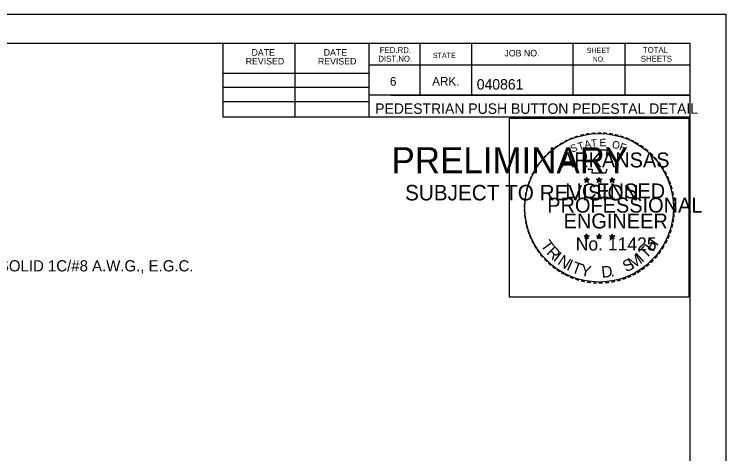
# Model space of a CAD drawing. Extents: x 1370050 to 1370716, y 380076 to 380502.
# Drawn here: x 1370525.6 to 1370716.4, y 380384.6 to 380502.4 of the extents above; entities that cross this region are included whole.
import ezdxf

# ---------------------------------------------------------------- set-up
doc = ezdxf.new("R2010")
doc.units = 0
for name, color, linetype in [('R_Border', 7, 'Continuous'), ('R_Border PE', 7, 'Continuous'), ('R_Border Prem', 7, 'Continuous'), ('R_Grid', 7, 'Continuous'), ('R_No Plot', 7, 'Continuous')]:
    doc.layers.add(name, color=color, linetype=linetype)

msp = doc.modelspace()

# ---------------------------------------------------------------- linework, layer by layer
at = {"layer": 'R_Border'}
for p, q in [((1370074.49, 380494.58), (1370706.85, 380494.58)), ((1370581.57, 380474.82), (1370581.57, 380494.58)), ((1370600.93, 380474.82), (1370600.93, 380494.58)), ((1370620.65, 380494.58), (1370620.65, 380474.82)), ((1370634.33, 380494.58), (1370634.33, 380480.7)), ((1370648.21, 380494.58), (1370648.21, 380480.7)), ((1370675.37, 380494.58), (1370675.37, 380480.7)), ((1370689.25, 380494.58), (1370689.25, 380480.7)), ((1370706.85, 380083.66), (1370706.85, 380494.58)), ((1370706.85, 380488.74), (1370706.85, 380488.74)), ((1370706.85, 380488.7), (1370620.65, 380488.7)), ((1370581.57, 380486.54), (1370620.65, 380486.54)), ((1370581.57, 380482.82), (1370620.65, 380482.82)), ((1370706.85, 380480.7), (1370620.65, 380480.7)), ((1370626.57, 380480.7), (1370706.85, 380480.7)), ((1370581.57, 380478.94), (1370620.65, 380478.94)), ((1370706.85, 380474.82), (1370581.57, 380474.82))]:
    msp.add_line(p, q, dxfattribs=at)
at = {"layer": 'R_Border PE'}
for p, q in [((1370679.06, 380458.65), (1370678.98, 380458.14)), ((1370679.06, 380457.92), (1370679.06, 380458.65)), ((1370679.06, 380458.65), (1370679.16, 380458.15)), ((1370682.4, 380458.65), (1370682.32, 380458.14)), ((1370682.4, 380457.92), (1370682.4, 380458.65)), ((1370682.4, 380458.65), (1370682.5, 380458.15)), ((1370685.93, 380458.62), (1370685.84, 380458.12)), ((1370685.93, 380457.89), (1370685.93, 380458.62)), ((1370685.93, 380458.62), (1370686.02, 380458.12)), ((1370678.36, 380458.14), (1370679.06, 380457.92)), ((1370678.36, 380458.14), (1370678.87, 380458.05)), ((1370678.36, 380458.14), (1370678.83, 380457.9)), ((1370678.63, 380457.32), (1370679.06, 380457.92)), ((1370678.63, 380457.32), (1370678.88, 380457.81)), ((1370678.63, 380457.32), (1370679.05, 380457.76)), ((1370679.48, 380457.32), (1370679.05, 380457.75)), ((1370679.75, 380458.14), (1370679.06, 380457.92)), ((1370679.48, 380457.32), (1370679.06, 380457.92)), ((1370679.75, 380458.14), (1370679.18, 380458.04)), ((1370679.48, 380457.32), (1370679.21, 380457.91)), ((1370679.75, 380458.14), (1370679.34, 380457.94)), ((1370681.7, 380458.14), (1370682.4, 380457.92)), ((1370681.7, 380458.14), (1370682.21, 380458.05)), ((1370681.7, 380458.14), (1370682.17, 380457.9)), ((1370681.97, 380457.32), (1370682.4, 380457.92)), ((1370681.97, 380457.32), (1370682.22, 380457.81)), ((1370681.97, 380457.32), (1370682.39, 380457.76)), ((1370682.82, 380457.32), (1370682.39, 380457.75)), ((1370683.09, 380458.14), (1370682.4, 380457.92)), ((1370682.82, 380457.32), (1370682.4, 380457.92)), ((1370683.09, 380458.14), (1370682.52, 380458.04)), ((1370682.82, 380457.32), (1370682.55, 380457.91)), ((1370683.09, 380458.14), (1370682.68, 380457.94)), ((1370685.23, 380458.12), (1370685.93, 380457.89)), ((1370685.23, 380458.12), (1370685.73, 380458.03)), ((1370685.23, 380458.12), (1370685.7, 380457.87)), ((1370685.49, 380457.3), (1370685.93, 380457.89)), ((1370685.49, 380457.3), (1370685.75, 380457.79)), ((1370685.49, 380457.3), (1370685.92, 380457.73)), ((1370686.35, 380457.3), (1370685.92, 380457.73)), ((1370686.62, 380458.12), (1370685.93, 380457.89)), ((1370686.35, 380457.3), (1370685.93, 380457.89)), ((1370686.62, 380458.12), (1370686.05, 380458.02)), ((1370686.35, 380457.3), (1370686.08, 380457.88)), ((1370686.62, 380458.12), (1370686.21, 380457.91)), ((1370678.35, 380442.99), (1370679.05, 380442.77)), ((1370678.35, 380442.99), (1370678.86, 380442.9)), ((1370678.35, 380442.99), (1370678.83, 380442.75)), ((1370679.05, 380443.5), (1370678.97, 380443)), ((1370679.05, 380442.77), (1370679.05, 380443.5)), ((1370679.05, 380443.5), (1370679.15, 380443)), ((1370679.74, 380442.99), (1370679.05, 380442.77)), ((1370679.74, 380442.99), (1370679.17, 380442.9)), ((1370679.74, 380442.99), (1370679.34, 380442.79)), ((1370681.69, 380442.99), (1370682.39, 380442.77)), ((1370681.69, 380442.99), (1370682.2, 380442.9)), ((1370681.69, 380442.99), (1370682.16, 380442.75)), ((1370682.39, 380443.5), (1370682.31, 380443)), ((1370682.39, 380442.77), (1370682.39, 380443.5)), ((1370682.39, 380443.5), (1370682.49, 380443)), ((1370683.08, 380442.99), (1370682.39, 380442.77)), ((1370683.08, 380442.99), (1370682.51, 380442.9)), ((1370683.08, 380442.99), (1370682.67, 380442.79)), ((1370685.22, 380442.97), (1370685.92, 380442.75)), ((1370685.22, 380442.97), (1370685.73, 380442.88)), ((1370685.22, 380442.97), (1370685.7, 380442.73)), ((1370685.92, 380443.48), (1370685.84, 380442.98)), ((1370685.92, 380442.75), (1370685.92, 380443.48)), ((1370685.92, 380443.48), (1370686.02, 380442.98)), ((1370686.62, 380442.97), (1370685.92, 380442.75)), ((1370686.62, 380442.97), (1370686.04, 380442.88)), ((1370686.62, 380442.97), (1370686.21, 380442.77)), ((1370678.62, 380442.18), (1370679.05, 380442.77)), ((1370678.62, 380442.18), (1370678.87, 380442.67)), ((1370678.62, 380442.18), (1370679.05, 380442.61)), ((1370679.48, 380442.18), (1370679.05, 380442.77)), ((1370679.48, 380442.18), (1370679.05, 380442.61)), ((1370679.48, 380442.18), (1370679.2, 380442.76)), ((1370681.96, 380442.18), (1370682.39, 380442.77)), ((1370681.96, 380442.18), (1370682.21, 380442.67)), ((1370681.96, 380442.18), (1370682.38, 380442.61)), ((1370682.81, 380442.18), (1370682.38, 380442.61)), ((1370682.81, 380442.18), (1370682.39, 380442.77)), ((1370682.81, 380442.18), (1370682.54, 380442.76)), ((1370685.49, 380442.16), (1370685.92, 380442.75)), ((1370685.49, 380442.16), (1370685.74, 380442.65)), ((1370685.49, 380442.16), (1370685.92, 380442.59)), ((1370686.35, 380442.16), (1370685.92, 380442.75)), ((1370686.35, 380442.16), (1370685.92, 380442.59)), ((1370686.35, 380442.16), (1370686.07, 380442.74))]:
    msp.add_line(p, q, dxfattribs=at)
for points in [[(1370678.44, 380465.9), (1370678.98, 380464.24)], [(1370685.46, 380464.05), (1370685.75, 380464.62), (1370684.38, 380464.57), (1370684.67, 380465.9), (1370678.44, 380465.9)], [(1370679.43, 380461.05), (1370679.43, 380460.88), (1370680.55, 380460.84), (1370680.44, 380459.89), (1370684.18, 380459.89), (1370684.59, 380460.96)], [(1370679.06, 380458.65), (1370679.48, 380457.32), (1370678.36, 380458.14), (1370679.75, 380458.14), (1370678.63, 380457.32), (1370679.06, 380458.65)], [(1370682.4, 380458.65), (1370682.82, 380457.32), (1370681.7, 380458.14), (1370683.09, 380458.14), (1370681.97, 380457.32), (1370682.4, 380458.65)], [(1370685.93, 380458.62), (1370686.35, 380457.3), (1370685.23, 380458.12), (1370686.62, 380458.12), (1370685.49, 380457.3), (1370685.93, 380458.62)], [(1370679.05, 380443.5), (1370679.48, 380442.18), (1370678.35, 380442.99), (1370679.74, 380442.99), (1370678.62, 380442.18), (1370679.05, 380443.5)], [(1370682.39, 380443.5), (1370682.81, 380442.18), (1370681.69, 380442.99), (1370683.08, 380442.99), (1370681.96, 380442.18), (1370682.39, 380443.5)], [(1370685.92, 380443.48), (1370686.35, 380442.16), (1370685.22, 380442.97), (1370686.62, 380442.97), (1370685.49, 380442.16), (1370685.92, 380443.48)]]:
    msp.add_lwpolyline(points, dxfattribs=at)
for centre, radius in [((1370679.06, 380457.92), 0.344), ((1370682.4, 380457.92), 0.344), ((1370685.92, 380457.89), 0.344), ((1370679.06, 380457.92), 0.289), ((1370679.06, 380457.92), 0.231), ((1370679.06, 380457.92), 0.198), ((1370679.06, 380457.92), 0.149), ((1370679.06, 380457.92), 0.0991), ((1370679.06, 380457.92), 0.0593), ((1370682.4, 380457.92), 0.289), ((1370682.4, 380457.92), 0.231), ((1370682.4, 380457.92), 0.198), ((1370682.4, 380457.92), 0.149), ((1370682.4, 380457.92), 0.0991), ((1370682.4, 380457.92), 0.0593), ((1370685.92, 380457.89), 0.289), ((1370685.92, 380457.89), 0.231), ((1370685.92, 380457.89), 0.198), ((1370685.92, 380457.89), 0.149), ((1370685.92, 380457.89), 0.0991), ((1370685.92, 380457.89), 0.0593), ((1370679.05, 380442.77), 0.344), ((1370679.05, 380442.77), 0.289), ((1370679.05, 380442.77), 0.231), ((1370679.05, 380442.77), 0.198), ((1370682.39, 380442.77), 0.344), ((1370682.39, 380442.77), 0.289), ((1370682.39, 380442.77), 0.231), ((1370682.39, 380442.77), 0.198), ((1370685.92, 380442.75), 0.344), ((1370685.92, 380442.75), 0.289), ((1370685.92, 380442.75), 0.231), ((1370685.92, 380442.75), 0.198), ((1370679.05, 380442.77), 0.149), ((1370679.05, 380442.77), 0.0991), ((1370679.05, 380442.77), 0.0593), ((1370682.39, 380442.77), 0.149), ((1370682.39, 380442.77), 0.0991), ((1370682.39, 380442.77), 0.0593), ((1370685.92, 380442.75), 0.149), ((1370685.92, 380442.75), 0.0991), ((1370685.92, 380442.75), 0.0593)]:
    msp.add_circle(centre, radius, dxfattribs=at)
at = {"layer": 'R_No Plot'}
for p, q in [((1370049.68, 380502.37), (1370716.35, 380502.37)), ((1370658.26, 380428.72), (1370658.26, 380428.72))]:
    msp.add_line(p, q, dxfattribs=at)
for points in [[(1370049.67, 380502.37), (1370716.35, 380502.37), (1370716.35, 380075.69), (1370049.67, 380075.69)], [(1370658.41, 380474.51), (1370706.41, 380474.51), (1370706.41, 380426.51), (1370658.41, 380426.51)]]:
    msp.add_lwpolyline(points, close=True, dxfattribs=at)
msp.add_circle((1370682.41, 380450.51), 19.9, dxfattribs=at)

# ---------------------------------------------------------------- texts
at = {"layer": 'R_Border'}
for s, height, p in [('DATE', 1.758, (1370589.21, 380491.26)), ('DATE', 1.758, (1370608.57, 380491.26)), ('FED.RD.', 1.564, (1370623.61, 380492.02)), ('JOB NO.', 1.758, (1370657.01, 380491.06)), ('SHEET', 1.368, (1370679.09, 380492.02)), ('TOTAL', 1.564, (1370694.13, 380492.02)), ('REVISED', 1.758, (1370587.65, 380488.9)), ('REVISED', 1.758, (1370607.01, 380488.9)), ('DIST.NO.', 1.564, (1370623.21, 380489.66)), ('STATE', 1.368, (1370637.85, 380490.66)), ('NO.', 1.368, (1370680.65, 380489.66)), ('SHEETS', 1.564, (1370693.57, 380489.66)), ('6', 2.34, (1370626.33, 380483.22)), ('ARK.', 2.345, (1370637.65, 380483.22)), ('040861', 2.8, (1370649.6, 380482.18)), ('PEDESTRIAN PUSH BUTTON PEDESTAL DETAIL', 2.8, (1370622.37, 380475.68))]:
    msp.add_text(s, height=height, dxfattribs=at).set_placement(p)
at = {"layer": 'R_Border PE'}
for s, height, rotation, p in [('-', 3.2, 19.1761, (1370675.94, 380468.15)), ('-', 3.2, 13.6302, (1370677.44, 380468.63)), ('-', 3.2, 10.2193, (1370678.79, 380468.96)), ('-', 3.2, 5.8968, (1370680.25, 380469.18)), ('-', 3.2, 0.1862, (1370681.79, 380469.32)), ('-', 3.2, 357.743, (1370683.24, 380469.29)), ('-', 3.2, 352.1617, (1370684.73, 380469.18)), ('-', 3.2, 347.2049, (1370686.17, 380468.95)), ('-', 3.2, 342.3362, (1370687.44, 380468.64)), ('-', 3.2, 34.0636, (1370672.21, 380466.24)), ('-', 3.2, 28.7918, (1370673.4, 380466.98)), ('-', 3.2, 24.3072, (1370674.67, 380467.61)), ('T', 2, 16.4036, (1370676.98, 380465.91)), ('A', 2, 11.2132, (1370678.63, 380466.42)), ('T', 2, 6.0228, (1370680.33, 380466.75)), ('E', 2, 0.8323, (1370682.54, 380466.97)), ('O', 2, 350.4515, (1370685.75, 380466.55)), ('F', 2, 340.0707, (1370687.65, 380466.09)), ('-', 3.2, 337.8551, (1370688.91, 380468.2)), ('-', 3.2, 334.1211, (1370690.17, 380467.66)), ('-', 3.2, 329.6409, (1370691.33, 380467.09)), ('-', 3.2, 38.9507, (1370670.1, 380464.69)), ('-', 3.2, 36.2317, (1370671.05, 380465.45)), ('S', 2, 21.594, (1370675.15, 380465.25)), ('-', 3.2, 325.8627, (1370692.61, 380466.37)), ('-', 3.2, 320.5297, (1370693.83, 380465.52)), ('-', 3.2, 48.4231, (1370668.34, 380462.9)), ('-', 3.2, 42.9622, (1370669.23, 380463.86)), ('-', 3.2, 315.5786, (1370695.03, 380464.54)), ('-', 3.2, 309.8797, (1370696.17, 380463.44)), ('-', 3.2, 54.2325, (1370666.71, 380460.8)), ('-', 3.2, 50.6142, (1370667.53, 380461.93)), ('-', 3.2, 306.6522, (1370697.22, 380462.24)), ('-', 3.2, 62.8713, (1370665.43, 380458.51)), ('-', 3.2, 58.0706, (1370666.06, 380459.74)), ('-', 2.8, 303.6753, (1370698.19, 380461.1)), ('-', 3.2, 299.6684, (1370698.83, 380459.89)), ('-', 3.2, 67.7743, (1370664.91, 380457.29)), ('-', 3.2, 294.6628, (1370699.48, 380458.66)), ('-', 3.2, 72.3945, (1370664.47, 380456.03)), ('-', 3.2, 290.5728, (1370699.99, 380457.51)), ('-', 3.2, 285.1233, (1370700.46, 380456.35)), ('-', 3.2, 81.2013, (1370663.82, 380453.18)), ('-', 3.2, 75.461, (1370664.08, 380454.6)), ('-', 3.2, 280.5493, (1370700.86, 380454.86)), ('-', 3.2, 85.1863, (1370663.66, 380451.8)), ('-', 3.2, 276.5962, (1370701.18, 380453.33)), ('-', 3.2, 89.0622, (1370663.61, 380450.39)), ('-', 3.2, 274.3301, (1370701.3, 380451.88)), ('-', 3.2, 94.1959, (1370663.68, 380448.94)), ('-', 3.2, 263.5172, (1370701.33, 380449.29)), ('-', 3.2, 269.9407, (1370701.37, 380450.62)), ('-', 3.2, 98.9479, (1370663.83, 380447.61)), ('-', 3.2, 101.7149, (1370664.1, 380446.14)), ('-', 3.2, 260.9953, (1370701.19, 380447.98)), ('-', 3.2, 105.4578, (1370664.42, 380444.95)), ('-', 3.2, 255.7626, (1370700.97, 380446.62)), ('-', 3.2, 109.0874, (1370664.85, 380443.69)), ('-', 3.2, 114.0643, (1370665.36, 380442.5)), ('-', 3.2, 247.8887, (1370700.16, 380443.84)), ('-', 3.2, 252.8681, (1370700.61, 380445.18)), ('-', 3.2, 115.7289, (1370665.97, 380441.26)), ('T', 3.08, 306.0406, (1370666.57, 380440.45)), ('H', 3.08, 54.6088, (1370696.81, 380438.52)), ('-', 3.2, 244.6197, (1370699.64, 380442.58)), ('-', 3.2, 120.4471, (1370666.68, 380440.09)), ('-', 3.2, 125.8934, (1370667.49, 380438.97)), ('R', 3.08, 314.005, (1370668.09, 380438.35)), ('T', 3.08, 46.6444, (1370695.03, 380436.63)), ('-', 3.2, 239.0712, (1370698.85, 380441.08)), ('-', 3.2, 130.7181, (1370668.41, 380437.87)), ('I', 3.08, 321.9694, (1370669.89, 380436.49)), ('N', 3.08, 326.5002, (1370671.03, 380435.54)), ('M', 3.08, 32.6563, (1370691.34, 380433.98)), ('I', 3.08, 42.1136, (1370693.91, 380435.68)), ('-', 3.2, 231.2538, (1370697.19, 380438.64)), ('-', 3.2, 233.8452, (1370698.05, 380439.77)), ('-', 3.2, 134.2238, (1370669.45, 380436.78)), ('-', 3.2, 138.9338, (1370670.5, 380435.85)), ('I', 3.08, 335.3603, (1370673.44, 380433.97)), ('T', 3.08, 339.8912, (1370674.77, 380433.32)), ('Y', 3.08, 347.8556, (1370677.2, 380432.43)), ('S', 3.08, 26.9312, (1370689.66, 380433.17)), ('-', 3.2, 221.0851, (1370695.18, 380436.49)), ('-', 3.2, 225.7653, (1370696.23, 380437.51)), ('-', 3.2, 144.6463, (1370671.61, 380435.04)), ('-', 3.2, 148.0898, (1370672.73, 380434.29)), ('D', 3.08, 6.3969, (1370683.17, 380431.71)), ('-', 3.2, 212.2491, (1370693.02, 380434.77)), ('-', 3.2, 215.7363, (1370694.09, 380435.55)), ('-', 3.2, 151.5704, (1370673.89, 380433.64)), ('-', 3.2, 154.6002, (1370674.93, 380433.15)), ('-', 3.2, 158.5612, (1370676.18, 380432.64)), ('-', 3.2, 162.7983, (1370677.56, 380432.22)), ('.', 3.08, 13.7642, (1370685.55, 380431.97)), ('-', 3.2, 200.7184, (1370689.42, 380432.9)), ('-', 3.2, 204.2516, (1370690.65, 380433.44)), ('-', 3.2, 207.3568, (1370691.9, 380434.08)), ('-', 3.2, 167.5555, (1370678.99, 380431.89)), ('-', 3.2, 173.1155, (1370680.53, 380431.67)), ('-', 3.2, 176.5183, (1370682.03, 380431.56)), ('-', 3.2, 181.5918, (1370683.51, 380431.6)), ('-', 3.2, 185.8167, (1370685.13, 380431.75)), ('-', 3.2, 191.2858, (1370686.6, 380432.02)), ('-', 3.2, 195.4743, (1370688.06, 380432.41))]:
    msp.add_text(s, height=height, rotation=rotation, dxfattribs=at).set_placement(p)
for s, height, p in [('ARKANSAS', 4, (1370672.15, 380461.32)), ('LICENSED', 4, (1370673.34, 380453.02)), ('DWB', 0.02, (1370679.03, 380457.91)), ('DWB', 0.02, (1370682.37, 380457.91)), ('DWB', 0.02, (1370685.9, 380457.89)), ('PROFESSIONAL', 4, (1370668.49, 380449.21)), ('ENGINEER', 4, (1370672.87, 380444.96)), ('No. 11425', 3.514, (1370676.12, 380439.06)), ('DWB', 0.02, (1370679.02, 380442.76)), ('DWB', 0.02, (1370682.36, 380442.76)), ('DWB', 0.02, (1370685.9, 380442.74))]:
    msp.add_text(s, height=height, dxfattribs=at).set_placement(p)
at = {"layer": 'R_Border Prem'}
for s, height, p in [('PRELIMINARY', 7, (1370626.75, 380459.74)), ('SUBJECT TO REVISION', 4.1502, (1370630.37, 380452.48))]:
    msp.add_text(s, height=height, dxfattribs=at).set_placement(p)
at = {"layer": 'R_Grid'}
msp.add_text(' 1/2" NMC WITH A SOLID 1C/#8 A.W.G., E.G.C.', height=3, dxfattribs=at).set_placement((1370486.86, 380433.45))

doc.saveas('drawing.dxf')
